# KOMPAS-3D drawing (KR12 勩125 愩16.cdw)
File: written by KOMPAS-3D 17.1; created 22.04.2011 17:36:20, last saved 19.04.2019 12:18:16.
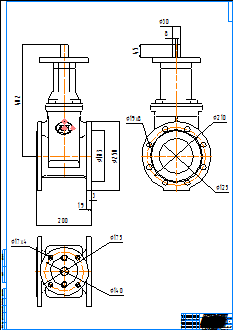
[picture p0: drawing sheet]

Title block, sheet 1: name: KR12 Ду125 Ру16; material: Внимание! Данный продукт является объектом авторского права ООО «Торговый Дом АДЛ». / Запрещается изменение, копирование, распространение / (в том числе путем копирования на другие сайты и ресурсы в Интернете) / или любое иное использование информации и объектов без предварительного / согласия правообладателя (ООО «Торговый Дом АДЛ»).; scale: 1:1; sheets: 1; organisation: ООО "Торговый дом АДЛ"; sheet format: A0; stored path: \\adlc.lan\data\АДЛ_ПКД\3D-модели\ADL production\Клиновые задвижки серии KR ГРАНАР\Клиновые задвижки KR12\KOMPAS 2D\KR12 Ду125 Ру16.cdw

Views: Спереди 4, Проекционный вид 5, Проекционный вид 6
Dimensions and other numbers on the sheet: 250; 183; 402; 3; 19; 200; 175; 17; 140; 8; 30; 45; 210; 125; 1:1; 1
